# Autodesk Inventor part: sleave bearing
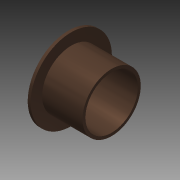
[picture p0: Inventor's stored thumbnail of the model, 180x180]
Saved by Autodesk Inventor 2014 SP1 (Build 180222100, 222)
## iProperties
Created: 2014-04
Part Number: sleave bearing
Material: Bronze, Cast
Document SubType Name: Modeling
Designer: BobvH
Density: 8.87 g/cm^3
Appearance: Bronze - Satin
Mass: 10722.9 g
Surface Area: 2563.59 cm^2
Volume: 1208.9 cm^3
Author: BobvH
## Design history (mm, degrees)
sketch "Sketch1"
  geometry: L1 (0, 0)-(-275.581, 0); L2 (0, -91)-(-150, -91); L3 (-150, -91)-(-150, -141); L4 (-150, -141)-(-140, -141); L5 (-140, -141)-(-140, -101); L6 (-140, -101)-(0, -101); L7 (0, -101)-(0, -91)
  constraints: 14 end point, 5 parallel, 1 horizontal, 1 perpendicular
  dimensions: "d0" = 91 distance between parallel lines of L1 L2; "d1" = 10 distance of L6.end L2.start; "d2" = 150 distance of L2.start L2.end; "d3" = 0 horizontal distance of L1.start L2.start; "d4" = 10 distance of L3.end L4.end; "d5" = 50 distance between parallel lines of L2 L4
revolve "Revolution1" sketch "Sketch1" stored, may be unused: angle "d6" = 90 deg
sketch "Sketch2"
  geometry: L1 (-7.017, -106.164)-(0, -106.164); L2 (0, -106.164)-(0, -141); L3 (0, -141)-(-7.017, -141); L4 (-7.017, -141)-(-7.017, -106.164); 1 further point
  constraints: 8 end point, 2 parallel, 1 horizontal, 1 perpendicular, 1 vertical alignment, 1 other
extrude "Extrusion1" join sketch "Sketch2" distance "d7" = 0.05; taper "d8" = 0 deg
body "Solid1"
